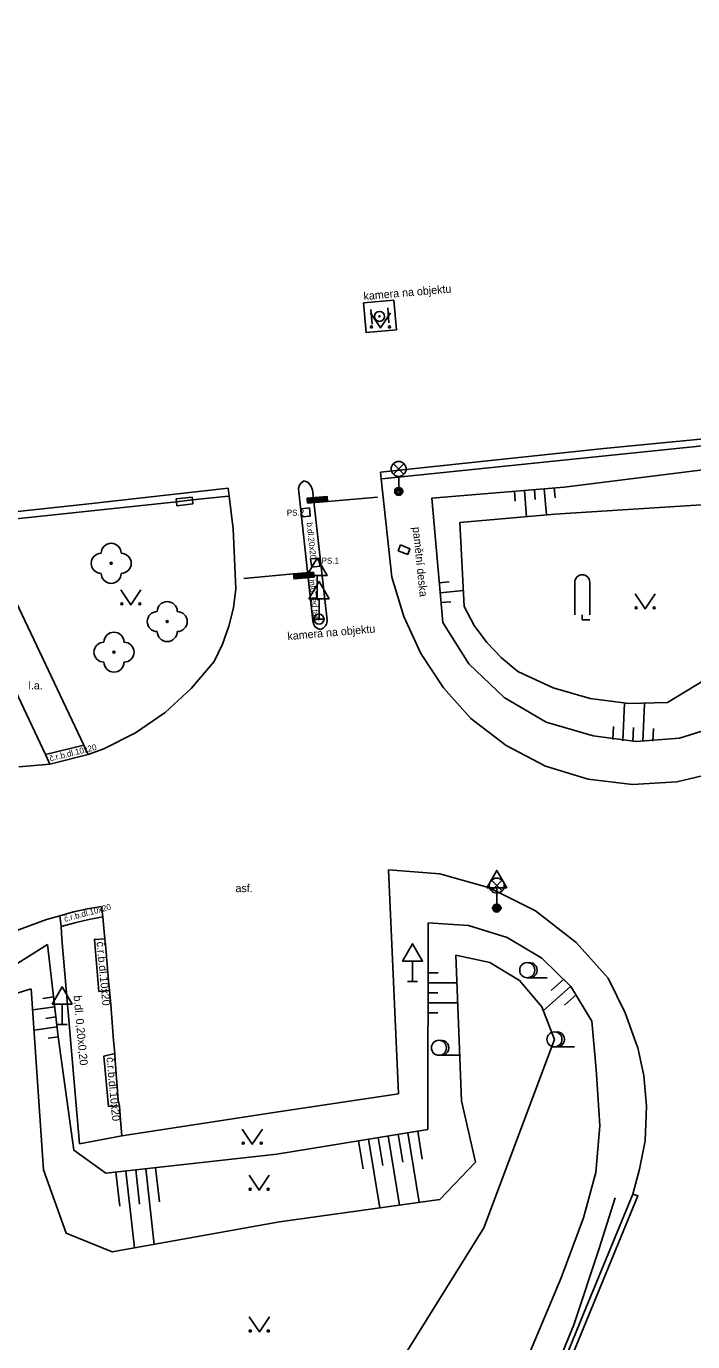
# Model space of a CAD drawing. Extents: x -599951 to -598963, y -1164095 to -1162939.
# Drawn here: x -599157.1 to -599123.8, y -1163520.6 to -1163454.9 of the extents above; entities that cross this region are included whole.
import ezdxf

# ---------------------------------------------------------------- set-up
doc = ezdxf.new("R2010")
doc.units = 0
for name, color, linetype in [('Level 10', 7, 'Continuous'), ('Level 11', 7, 'Continuous'), ('Level 14', 7, 'Continuous'), ('Level 15', 7, 'Continuous'), ('Level 22', 7, 'Continuous'), ('Level 24', 7, 'Continuous'), ('Level 25', 7, 'Continuous'), ('Level 33', 7, 'Continuous'), ('Level 34', 7, 'Continuous'), ('Level 36', 7, 'Continuous'), ('Level 40', 7, 'Continuous'), ('Level 42', 7, 'Continuous'), ('Level 7', 7, 'Continuous'), ('Level 9', 7, 'Continuous')]:
    doc.layers.add(name, color=color, linetype=linetype)

msp = doc.modelspace()

# ---------------------------------------------------------------- linework, layer by layer
at = {"layer": 'Level 10'}
for points in [[(-599139.38, -1163477.16), (-599128.22, -1163475.98), (-599120.64, -1163475.24), (-599111.07, -1163457.98), (-599101.3, -1163440.49), (-599098.73, -1163435.9), (-599095.61, -1163430.32), (-599094.65, -1163428.55), (-599093.67, -1163426.81), (-599088.68, -1163417.86), (-599084.69, -1163410.72), (-599084.25, -1163409.97), (-599084.5, -1163407.96), (-599084.75, -1163405.96), (-599085.26, -1163400.92)], [(-599143.46, -1163478.13), (-599143.48, -1163477.97), (-599143.43, -1163477.81), (-599143.33, -1163477.67), (-599143.19, -1163477.59)], [(-599143.19, -1163477.59), (-599142.99, -1163477.67), (-599142.85, -1163477.83), (-599142.78, -1163478.03)], [(-599139.38, -1163477.16), (-599139.34, -1163477.49), (-599138.81, -1163482.4)], [(-599154.1, -1163478.75), (-599146.99, -1163477.96)], [(-599146.99, -1163477.96), (-599146.94, -1163478.35), (-599146.74, -1163479.99), (-599146.6, -1163482.98)], [(-599143.46, -1163478.13), (-599142.76, -1163484.59)], [(-599142.78, -1163478.03), (-599142.05, -1163484.55)], [(-599154.1, -1163478.75), (-599159.37, -1163479.32)], [(-599146.6, -1163482.98), (-599146.72, -1163483.93), (-599146.95, -1163484.85)], [(-599134.86, -1163489.46), (-599136.23, -1163487.93), (-599137.36, -1163486.22), (-599138.22, -1163484.36), (-599138.81, -1163482.4)], [(-599146.95, -1163484.85), (-599147.27, -1163485.75)], [(-599142.38, -1163485.02), (-599142.53, -1163484.97), (-599142.65, -1163484.87), (-599142.73, -1163484.74), (-599142.76, -1163484.59)], [(-599142.05, -1163484.55), (-599142.06, -1163484.7), (-599142.13, -1163484.84), (-599142.24, -1163484.95), (-599142.38, -1163485.02)], [(-599147.27, -1163485.75), (-599147.68, -1163486.61)], [(-599147.68, -1163486.61), (-599148.83, -1163487.97), (-599150.14, -1163489.17), (-599151.61, -1163490.18), (-599153.2, -1163490.98)], [(-599116.17, -1163487.48), (-599117.82, -1163489.4), (-599119.82, -1163490.94), (-599122.11, -1163492.04), (-599124.57, -1163492.63)], [(-599124.57, -1163492.63), (-599126.79, -1163492.77), (-599129, -1163492.5), (-599131.13, -1163491.85), (-599133.1, -1163490.82), (-599134.86, -1163489.46)], [(-599153.2, -1163490.98), (-599153.98, -1163491.27), (-599155.89, -1163491.75)], [(-599155.89, -1163491.75), (-599157.44, -1163491.88)], [(-599138.48, -1163508.22), (-599138.98, -1163497.03)], [(-599138.98, -1163497.03), (-599136.42, -1163497.23), (-599133.94, -1163497.92), (-599131.64, -1163499.08), (-599129.61, -1163500.66)], [(-599156.06, -1163499.5), (-599155.4, -1163499.32)], [(-599155.4, -1163499.32), (-599154.72, -1163499.12), (-599154.02, -1163498.97), (-599153.32, -1163498.86)], [(-599152.94, -1163502.75), (-599153.12, -1163500.76), (-599153.14, -1163500.48), (-599153.21, -1163499.75), (-599153.24, -1163499.38), (-599153.32, -1163498.86)], [(-599161.91, -1163503.32), (-599160.68, -1163502.05), (-599159.27, -1163500.97), (-599157.72, -1163500.12), (-599156.06, -1163499.5)], [(-599129.61, -1163500.66), (-599128, -1163502.44)], [(-599128, -1163502.44), (-599127.15, -1163504.18), (-599126.63, -1163505.65), (-599126.53, -1163505.92), (-599126.23, -1163507.31), (-599126.09, -1163508.84)], [(-599152.94, -1163502.75), (-599152.91, -1163503.05), (-599152.85, -1163503.75)], [(-599152.85, -1163503.75), (-599152.71, -1163505.55), (-599152.65, -1163506.21), (-599152.63, -1163506.56), (-599152.48, -1163508.54), (-599152.42, -1163508.82), (-599152.36, -1163509.53)], [(-599152.36, -1163509.53), (-599152.29, -1163510.31), (-599144.7, -1163509.15), (-599138.48, -1163508.22)], [(-599126.09, -1163508.84), (-599126.16, -1163510.56), (-599126.44, -1163511.99), (-599126.78, -1163513.23)], [(-599126.78, -1163513.23), (-599129.24, -1163519.22), (-599133.93, -1163530.74), (-599137.49, -1163540.22), (-599140.64, -1163549.06), (-599142.9, -1163555.68)]]:
    msp.add_lwpolyline(points, dxfattribs=at)
at = {"layer": 'Level 11'}
for points in [[(-599140.23, -1163468.69), (-599138.72, -1163468.56)], [(-599138.72, -1163468.56), (-599138.58, -1163470.05), (-599140.1, -1163470.18), (-599140.23, -1163468.69)], [(-599139.14, -1163477.47), (-599139.34, -1163477.49)], [(-599147.13, -1163478.37), (-599146.94, -1163478.35)], [(-599143.34, -1163478.99), (-599142.93, -1163478.94), (-599142.89, -1163479.35), (-599143.3, -1163479.39)], [(-599143.34, -1163478.99), (-599143.3, -1163479.39)], [(-599159.47, -1163479.33), (-599159.51, -1163479.61), (-599154.19, -1163490.8), (-599153.98, -1163491.27)], [(-599156.11, -1163491.27), (-599161.52, -1163479.81)], [(-599138.02, -1163481.27), (-599138.49, -1163481.08), (-599138.38, -1163480.79)], [(-599138.38, -1163480.79), (-599137.91, -1163480.98), (-599138.02, -1163481.27)], [(-599142.41, -1163481.86), (-599142.81, -1163481.91), (-599142.87, -1163481.49), (-599142.45, -1163481.45)], [(-599142.41, -1163481.86), (-599142.45, -1163481.45)], [(-599156.11, -1163491.27), (-599154.19, -1163490.8)], [(-599155.89, -1163491.75), (-599156.11, -1163491.27)], [(-599152.29, -1163510.31), (-599154.41, -1163510.71), (-599155.29, -1163500.47), (-599155.33, -1163499.85), (-599155.4, -1163499.32)], [(-599155.33, -1163499.85), (-599154.64, -1163499.67), (-599153.94, -1163499.51), (-599153.24, -1163499.38)], [(-599152.91, -1163503.05), (-599153.44, -1163503.1), (-599153.67, -1163500.5), (-599153.14, -1163500.48)], [(-599152.42, -1163508.82), (-599152.96, -1163508.86), (-599153.19, -1163506.33), (-599152.65, -1163506.21)], [(-599144.09, -1163559.49), (-599143.86, -1163559.5), (-599139.89, -1163547.77), (-599135.74, -1163536.38), (-599130.95, -1163524.1), (-599126.52, -1163513.32), (-599126.78, -1163513.23)]]:
    msp.add_lwpolyline(points, dxfattribs=at)
at = {"layer": 'Level 14'}
for points in [[(-599116.74, -1163481.43), (-599108.6, -1163465.85), (-599105.54, -1163458.62), (-599112.78, -1163470.4), (-599117.11, -1163476.98), (-599118.43, -1163478.3), (-599120.21, -1163478.58), (-599130.67, -1163479.25), (-599135.41, -1163479.67)], [(-599119.82, -1163476.61), (-599130.2, -1163477.9)], [(-599136.27, -1163484.67), (-599136.82, -1163478.46), (-599130.2, -1163477.9)], [(-599135.41, -1163479.67), (-599135.2, -1163483.87)], [(-599132.52, -1163487.11), (-599133.34, -1163486.44), (-599134.07, -1163485.67), (-599134.7, -1163484.81), (-599135.2, -1163483.87)], [(-599136.27, -1163484.67), (-599134.96, -1163486.73)], [(-599119.27, -1163484.97), (-599121.86, -1163486.73), (-599125.04, -1163488.66)], [(-599131.1, -1163489.64), (-599133.2, -1163488.42), (-599134.96, -1163486.73)], [(-599125.04, -1163488.66), (-599126.98, -1163488.71), (-599128.9, -1163488.46), (-599130.76, -1163487.93), (-599132.52, -1163487.11)], [(-599131.1, -1163489.64), (-599128.76, -1163490.33)], [(-599124.45, -1163490.44), (-599122.37, -1163489.8)], [(-599124.45, -1163490.44), (-599126.61, -1163490.62), (-599128.76, -1163490.33)], [(-599137.02, -1163510), (-599137, -1163499.67)], [(-599137, -1163499.67), (-599134.98, -1163499.8), (-599133.06, -1163500.4), (-599131.32, -1163501.44)], [(-599161.5, -1163506.23), (-599160.45, -1163504.57), (-599159.16, -1163503.08), (-599157.67, -1163501.8), (-599156.01, -1163500.76)], [(-599137.02, -1163510), (-599144.55, -1163511.23), (-599153.09, -1163512.19), (-599154.69, -1163511.04), (-599155.47, -1163505.37), (-599156.01, -1163500.76)], [(-599135.62, -1163501.29), (-599135.34, -1163508.57), (-599134.63, -1163511.64), (-599136.41, -1163513.5), (-599144.43, -1163514.61)], [(-599135.62, -1163501.29), (-599133.92, -1163501.66), (-599132.44, -1163502.56), (-599131.32, -1163503.88), (-599130.69, -1163505.5)], [(-599131.32, -1163501.44), (-599129.88, -1163502.86)], [(-599159.22, -1163504.29), (-599158.69, -1163503.85), (-599158.1, -1163503.48), (-599157.48, -1163503.18), (-599156.82, -1163502.97)], [(-599144.43, -1163514.61), (-599152.78, -1163516.12), (-599155.08, -1163515.19), (-599156.21, -1163512.02), (-599156.82, -1163502.97)], [(-599129.88, -1163502.86), (-599128.82, -1163504.58)], [(-599146.01, -1163559.67), (-599144.36, -1163554.65), (-599143.64, -1163552.55), (-599141.13, -1163545.61), (-599140.28, -1163543.26), (-599139.35, -1163540.61), (-599136.64, -1163532.79), (-599134.33, -1163526.77), (-599133.2, -1163524.19), (-599130.36, -1163517.42), (-599129.24, -1163514.42), (-599128.63, -1163512.15), (-599128.42, -1163509.82), (-599128.42, -1163509.81), (-599128.58, -1163507.5), (-599128.61, -1163507.01), (-599128.82, -1163504.58)], [(-599134.22, -1163514.91), (-599130.69, -1163505.5)], [(-599134.22, -1163514.91), (-599138.96, -1163522.54), (-599140.54, -1163525.27), (-599142.69, -1163529.45), (-599143.36, -1163530.96), (-599149.2, -1163544.87), (-599150.99, -1163549.39), (-599153.94, -1163557.78), (-599154.29, -1163558.86), (-599154.63, -1163560.58), (-599154.65, -1163560.81), (-599154.68, -1163563.32), (-599154.3, -1163572.65), (-599154.26, -1163573.32), (-599154.23, -1163573.89), (-599153.97, -1163574.87), (-599153.42, -1163575.63), (-599152.36, -1163576.36), (-599151.38, -1163576.72)]]:
    msp.add_lwpolyline(points, dxfattribs=at)
at = {"layer": 'Level 15'}
for points in [[(-599132.65, -1163478.61), (-599132.69, -1163478.11)], [(-599132.08, -1163479.38), (-599132.19, -1163478.07)], [(-599131.65, -1163478.52), (-599131.69, -1163478.03)], [(-599131.09, -1163479.29), (-599131.2, -1163477.98)], [(-599130.66, -1163478.44), (-599130.7, -1163477.94)], [(-599135.95, -1163482.63), (-599136.45, -1163482.68)], [(-599135.24, -1163483.07), (-599136.4, -1163483.18)], [(-599135.86, -1163483.63), (-599136.36, -1163483.67)], [(-599127.19, -1163488.7), (-599127.27, -1163490.58)], [(-599126.19, -1163488.73), (-599126.27, -1163490.62)], [(-599127.74, -1163489.87), (-599127.77, -1163490.52)], [(-599126.74, -1163489.92), (-599126.77, -1163490.61)], [(-599125.74, -1163489.96), (-599125.77, -1163490.6)], [(-599137.01, -1163502.67), (-599135.57, -1163502.67)], [(-599137, -1163502.17), (-599136.5, -1163502.17)], [(-599130.86, -1163503.05), (-599130.21, -1163502.47)], [(-599155.7, -1163503.38), (-599156.24, -1163503.46)], [(-599137.01, -1163503.17), (-599136.51, -1163503.17)], [(-599131.23, -1163504.05), (-599129.89, -1163502.85)], [(-599130.19, -1163503.79), (-599129.59, -1163503.26)], [(-599155.64, -1163503.88), (-599156.75, -1163504.03)], [(-599137.01, -1163503.67), (-599135.53, -1163503.67)], [(-599155.59, -1163504.38), (-599156.1, -1163504.45)], [(-599137.01, -1163504.17), (-599136.51, -1163504.17)], [(-599155.53, -1163504.87), (-599156.68, -1163505.03)], [(-599155.97, -1163505.44), (-599155.47, -1163505.37)], [(-599140.25, -1163511.96), (-599140.47, -1163510.56)], [(-599139.42, -1163513.92), (-599139.98, -1163510.48)], [(-599139.26, -1163511.8), (-599139.49, -1163510.4)], [(-599138.43, -1163513.78), (-599138.99, -1163510.32)], [(-599138.27, -1163511.64), (-599138.5, -1163510.24)], [(-599137.44, -1163513.64), (-599138.01, -1163510.16)], [(-599137.29, -1163511.48), (-599137.51, -1163510.08)], [(-599150.61, -1163511.91), (-599150.41, -1163513.62)], [(-599152.59, -1163512.13), (-599152.4, -1163513.84)], [(-599152.1, -1163512.08), (-599151.66, -1163515.92)], [(-599151.6, -1163512.02), (-599151.41, -1163513.73)], [(-599151.1, -1163511.97), (-599150.68, -1163515.74)]]:
    msp.add_lwpolyline(points, dxfattribs=at)
at = {"layer": 'Level 22'}
for centre in [(-599152.83, -1163481.71), (-599150.03, -1163484.62), (-599152.69, -1163486.15)]:
    msp.add_circle(centre, 0.05, dxfattribs=at)
for centre, start, end in [((-599152.83, -1163481.21), 0, 180), ((-599153.33, -1163481.71), 90, 270), ((-599152.33, -1163481.71), 270, 90), ((-599152.83, -1163482.21), 180, 0), ((-599150.03, -1163484.12), 0, 180), ((-599150.53, -1163484.62), 90, 270), ((-599149.53, -1163484.62), 270, 90), ((-599152.69, -1163485.65), 0, 180), ((-599150.03, -1163485.12), 180, 0), ((-599153.19, -1163486.15), 90, 270), ((-599152.19, -1163486.15), 270, 90), ((-599152.69, -1163486.65), 180, 0)]:
    msp.add_arc(centre, 0.5, start, end, dxfattribs=at)
at = {"layer": 'Level 24'}
for points in [[(-599148.78, -1163478.4), (-599149.59, -1163478.48)], [(-599148.77, -1163478.54), (-599148.78, -1163478.4)], [(-599149.57, -1163478.63), (-599149.59, -1163478.48)], [(-599149.55, -1163478.84), (-599149.57, -1163478.63)], [(-599149.55, -1163478.84), (-599148.76, -1163478.74)], [(-599148.76, -1163478.74), (-599148.77, -1163478.54)]]:
    msp.add_lwpolyline(points, dxfattribs=at)
at = {"layer": 'Level 25'}
for points in [[(-599142.57, -1163483.15), (-599142.6, -1163483.15), (-599142.55, -1163483.53), (-599142.52, -1163483.53)], [(-599142.52, -1163483.53), (-599142.57, -1163483.15)]]:
    msp.add_lwpolyline(points, dxfattribs=at)
for centre, radius in [((-599139.43, -1163469.37), 0.25), ((-599139.43, -1163469.37), 0.0303), ((-599142.45, -1163484.5), 0.25), ((-599142.45, -1163484.5), 0.0303)]:
    msp.add_circle(centre, radius, dxfattribs=at)
at = {"layer": 'Level 33'}
for p, q in [((-599138.735, -1163477.26), (-599138.205, -1163476.73)), ((-599138.735, -1163476.73), (-599138.205, -1163477.26)), ((-599138.47, -1163477.37), (-599138.47, -1163478.12)), ((-599142.023, -1163478.618), (-599139.532, -1163478.412)), ((-599143.716, -1163482.239), (-599146.206, -1163482.46)), ((-599133.835, -1163498.08), (-599133.305, -1163497.55)), ((-599133.835, -1163497.55), (-599133.305, -1163498.08)), ((-599133.57, -1163498.19), (-599133.57, -1163498.94))]:
    msp.add_line(p, q, dxfattribs=at)
for points in [[(-599143.02, -1163478.7), (-599142.023, -1163478.618), (-599142.044, -1163478.369), (-599143.041, -1163478.451)], [(-599142.974, -1163478.646), (-599142.077, -1163478.572), (-599142.09, -1163478.422), (-599142.987, -1163478.497)], [(-599142.929, -1163478.592), (-599142.131, -1163478.526), (-599142.135, -1163478.476), (-599142.933, -1163478.542)], [(-599142.72, -1163482.15), (-599143.716, -1163482.239), (-599143.694, -1163482.488), (-599142.698, -1163482.399)], [(-599142.765, -1163482.204), (-599143.662, -1163482.284), (-599143.649, -1163482.433), (-599142.752, -1163482.354)], [(-599142.811, -1163482.258), (-599143.608, -1163482.329), (-599143.603, -1163482.379), (-599142.806, -1163482.308)]]:
    msp.add_lwpolyline(points, close=True, dxfattribs=at)
for centre, radius in [((-599138.47, -1163476.995), 0.375), ((-599138.47, -1163478.12), 0.2), ((-599138.47, -1163478.12), 0.145), ((-599138.47, -1163478.12), 0.0876), ((-599133.57, -1163497.815), 0.375), ((-599133.57, -1163498.94), 0.2), ((-599133.57, -1163498.94), 0.145), ((-599133.57, -1163498.94), 0.0876)]:
    msp.add_circle(centre, radius, dxfattribs=at)
at = {"layer": 'Level 34'}
for p, q in [((-599142.55, -1163482.322), (-599142.55, -1163483.34)), ((-599142.45, -1163483.482), (-599142.45, -1163484.5)), ((-599142.7, -1163484.5), (-599142.2, -1163484.5)), ((-599133.57, -1163497.922), (-599133.57, -1163498.94)), ((-599133.82, -1163498.94), (-599133.32, -1163498.94)), ((-599137.78, -1163501.582), (-599137.78, -1163502.6)), ((-599138.03, -1163502.6), (-599137.53, -1163502.6)), ((-599155.28, -1163503.732), (-599155.28, -1163504.75)), ((-599155.53, -1163504.75), (-599155.03, -1163504.75))]:
    msp.add_line(p, q, dxfattribs=at)
for points in [[(-599143.05, -1163482.322), (-599142.05, -1163482.322), (-599142.55, -1163481.456)], [(-599142.95, -1163483.482), (-599141.95, -1163483.482), (-599142.45, -1163482.616)], [(-599134.07, -1163497.922), (-599133.07, -1163497.922), (-599133.57, -1163497.056)], [(-599138.28, -1163501.582), (-599137.28, -1163501.582), (-599137.78, -1163500.716)], [(-599155.78, -1163503.732), (-599154.78, -1163503.732), (-599155.28, -1163502.866)]]:
    msp.add_lwpolyline(points, close=True, dxfattribs=at)
at = {"layer": 'Level 36'}
for p, q in [((-599129.675, -1163482.655), (-599129.675, -1163484.28)), ((-599128.925, -1163482.655), (-599128.925, -1163484.28)), ((-599132.05, -1163502.415), (-599131.05, -1163502.415)), ((-599130.69, -1163505.875), (-599129.69, -1163505.875)), ((-599136.46, -1163506.295), (-599135.46, -1163506.295))]:
    msp.add_line(p, q, dxfattribs=at)
for points in [[(-599139.88, -1163469.2), (-599139.38, -1163469.95), (-599138.88, -1163469.2)], [(-599152.35, -1163483.04), (-599151.85, -1163483.79), (-599151.35, -1163483.04)], [(-599126.66, -1163483.24), (-599126.16, -1163483.99), (-599125.66, -1163483.24)], [(-599129.3, -1163484.28), (-599129.3, -1163484.53), (-599128.925, -1163484.53)], [(-599146.28, -1163509.99), (-599145.78, -1163510.74), (-599145.28, -1163509.99)], [(-599145.94, -1163512.29), (-599145.44, -1163513.04), (-599144.94, -1163512.29)], [(-599145.93, -1163519.37), (-599145.43, -1163520.12), (-599144.93, -1163519.37)]]:
    msp.add_lwpolyline(points, dxfattribs=at)
for centre, radius in [((-599139.83, -1163469.9), 0.05), ((-599138.931, -1163469.9), 0.05), ((-599152.3, -1163483.74), 0.05), ((-599151.401, -1163483.74), 0.05), ((-599126.61, -1163483.94), 0.05), ((-599125.711, -1163483.94), 0.05), ((-599132.05, -1163502.04), 0.375), ((-599130.69, -1163505.5), 0.375), ((-599136.46, -1163505.92), 0.375), ((-599146.23, -1163510.69), 0.05), ((-599145.331, -1163510.69), 0.05), ((-599145.89, -1163512.99), 0.05), ((-599144.991, -1163512.99), 0.05), ((-599145.88, -1163520.07), 0.05), ((-599144.981, -1163520.07), 0.05)]:
    msp.add_circle(centre, radius, dxfattribs=at)
for centre, start, end in [((-599129.3, -1163482.655), 0, 180), ((-599131.925, -1163502.04), 260.40593, 99.59407), ((-599130.565, -1163505.5), 260.40593, 99.59407), ((-599136.335, -1163505.92), 260.40593, 99.59407)]:
    msp.add_arc(centre, 0.375, start, end, dxfattribs=at)
at = {"layer": 'Level 7'}
for points in [[(-599095.3, -1163430.51), (-599102.16, -1163442.87), (-599110.66, -1163458.14), (-599120.39, -1163475.54), (-599139.14, -1163477.47)], [(-599148.77, -1163478.54), (-599147.13, -1163478.37)], [(-599159.32, -1163479.67), (-599149.57, -1163478.63)], [(-599149.57, -1163478.63), (-599148.77, -1163478.54)]]:
    msp.add_lwpolyline(points, dxfattribs=at)
at = {"layer": 'Level 9'}
for points in [[(-599139.86, -1163469.02), (-599139.8, -1163469.76)], [(-599138.97, -1163469.7), (-599139.02, -1163468.95)], [(-599127.65, -1163513.42), (-599128.45, -1163515.95), (-599129.73, -1163519.76), (-599131.18, -1163523.35), (-599135.61, -1163534.49), (-599138.41, -1163542), (-599141.13, -1163549.58), (-599144.65, -1163560.09)]]:
    msp.add_lwpolyline(points, dxfattribs=at)

# ---------------------------------------------------------------- texts
at = {"layer": 'Level 40'}
for s, height, rotation, p in [('b.dl.20x20', 0.3, 276, (-599143.07, -1163479.68)), ('č.r.b.dl.10x20', 0.3, 14, (-599155.87, -1163491.61)), ('č.r.b.dl.10x20', 0.3, 15, (-599155.14, -1163499.63)), ('č.r.b.dl.10x20', 0.4, 275.32016, (-599153.56, -1163500.63)), ('b.dl. 0,20x0,20', 0.4, 275.26629, (-599154.71, -1163503.32)), ('č.r.b.dl.10x20', 0.4, 275.32016, (-599153.07, -1163506.4))]:
    msp.add_text(s, height=height, rotation=rotation, dxfattribs=at).set_placement(p)
for s, p in [('l.a.', (-599156.96, -1163488.01)), ('asf.', (-599146.62, -1163498.14))]:
    msp.add_text(s, height=0.4, dxfattribs=at).set_placement(p)
at = {"layer": 'Level 42'}
for s, height, rotation, p in [('kamera na objektu', 0.4, 5, (-599140.21, -1163468.56)), ('pamětní deska', 0.4, 276, (-599137.78, -1163479.91)), ('info. led tab.', 0.3, 276, (-599142.94, -1163482.53)), ('kamera na objektu', 0.4, 5, (-599144.01, -1163485.55))]:
    msp.add_text(s, height=height, rotation=rotation, dxfattribs=at).set_placement(p)
for s, p in [('PS.2', (-599144.06, -1163479.33)), ('PS.1', (-599142.32, -1163481.73))]:
    msp.add_text(s, height=0.3, dxfattribs=at).set_placement(p)

doc.saveas('drawing.dxf')
